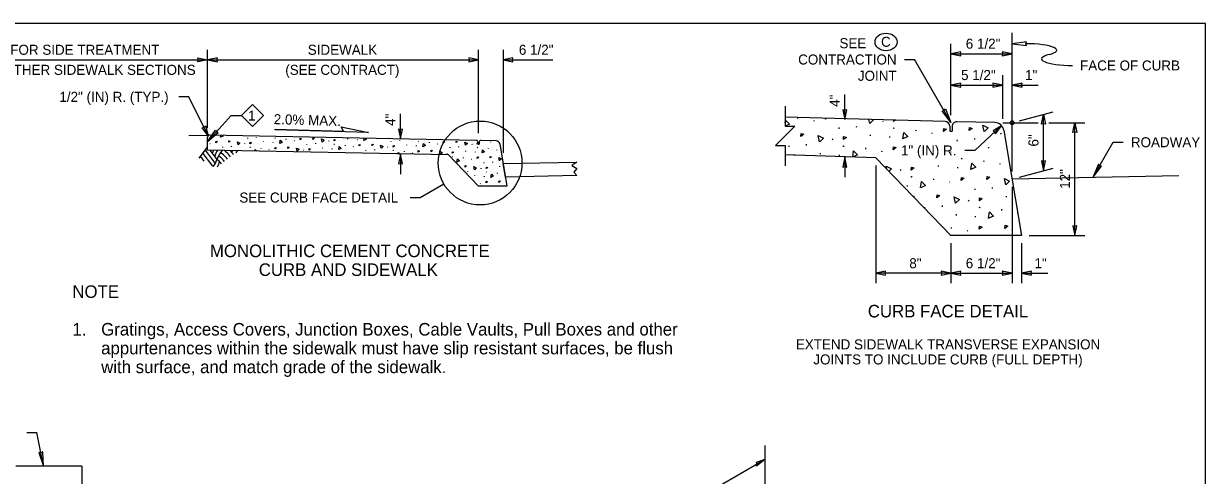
# Model space of a CAD drawing. Extents: x 99862 to 103151, y 100000 to 102076.
# Drawn here: x 101268 to 103151, y 101355 to 102076 of the extents above; entities that cross this region are included whole.
import ezdxf

# ---------------------------------------------------------------- set-up
doc = ezdxf.new("R2010")
doc.units = 0
for name, color, linetype in [('Level 1', 7, 'Continuous'), ('Level 13', 7, 'Continuous'), ('Level 15', 7, 'Continuous'), ('Level 20', 7, 'Continuous'), ('Level 27', 7, 'Continuous'), ('Level 28', 7, 'Continuous'), ('Level 34', 7, 'Continuous'), ('Level 6', 7, 'Continuous'), ('Level 60', 7, 'Continuous')]:
    doc.layers.add(name, color=color, linetype=linetype)

msp = doc.modelspace()

# ---------------------------------------------------------------- linework, layer by layer
at = {"layer": 'Level 1'}
msp.add_lwpolyline([(99862, 99999.5), (103151, 99999.5), (103151, 102075.5), (99862, 102075.5)], close=True, dxfattribs=at)
at = {"layer": 'Level 13'}
for p, q in [((102501.6, 101924.3), (102501.7, 101925.9)), ((102526.3, 101921.2), (102527.4, 101920.5)), ((102636.5, 101920.7), (102637.2, 101919.2)), ((102567.4, 101908), (102567.5, 101909.8)), ((102595.3, 101910.4), (102595.4, 101912.2)), ((102653.4, 101909.6), (102654.4, 101908.9)), ((102654.2, 101909.5), (102655.2, 101908.7)), ((102689.8, 101904.5), (102690, 101906.3)), ((102714.6, 101901.5), (102715.6, 101900.7)), ((102824.7, 101900.9), (102825.5, 101899.5)), ((101564.6, 101884.6), (101565.1, 101884.2)), ((101571.3, 101895.3), (101571.4, 101896.1)), ((101619.7, 101884.3), (101620, 101883.6)), ((101625.1, 101892.5), (101625.2, 101893.4)), ((101639.1, 101893.7), (101639.1, 101894.6)), ((101650.2, 101886.8), (101650.2, 101887.7)), ((101665.4, 101885.4), (101665.5, 101886.2)), ((101668.1, 101893.4), (101668.6, 101893)), ((101668.5, 101893.3), (101669, 101892.9)), ((101686.3, 101890.8), (101686.4, 101891.7)), ((101698.7, 101889.3), (101699.2, 101888.9)), ((101719.3, 101882.7), (101719.3, 101883.5)), ((101733.2, 101883.9), (101733.2, 101884.7)), ((101753.8, 101889), (101754.1, 101888.3)), ((101762.2, 101883.5), (101762.8, 101883.1)), ((101762.7, 101883.4), (101763.2, 101883)), ((101780.5, 101880.9), (101780.5, 101881.8)), ((101784.3, 101891.5), (101784.3, 101892.4)), ((101799.5, 101890), (101799.6, 101890.9)), ((101853.4, 101887.3), (101853.4, 101888.2)), ((101867.3, 101888.5), (101867.4, 101889.4)), ((101878.4, 101881.6), (101878.5, 101882.5)), ((101893.7, 101880.2), (101893.7, 101881)), ((101896.4, 101888.1), (101896.9, 101887.8)), ((101896.8, 101888.1), (101897.3, 101887.7)), ((101914.6, 101885.6), (101914.6, 101886.5)), ((101926.9, 101884), (101927.5, 101883.7)), ((101982, 101883.8), (101982.4, 101883)), ((102012.5, 101886.3), (102012.6, 101887.1)), ((102487.5, 101878.9), (102487.6, 101880.7)), ((102515.3, 101881.3), (102515.5, 101883.1)), ((102556.5, 101891.6), (102557.2, 101890.1)), ((102573.4, 101880.5), (102574.5, 101879.8)), ((102574.3, 101880.4), (102575.3, 101879.6)), ((102617.5, 101896.6), (102617.6, 101898.3)), ((102648, 101893.7), (102648.2, 101895.4)), ((102755.7, 101888.3), (102755.8, 101890)), ((102783.5, 101890.6), (102783.7, 101892.4)), ((101585.2, 101878), (101585.2, 101878.9)), ((101599.1, 101879.2), (101599.1, 101880.1)), ((101610.2, 101872.8), (101610.3, 101873.1)), ((101628.1, 101878.8), (101628.7, 101878.4)), ((101628.5, 101878.7), (101629.1, 101878.4)), ((101646.4, 101876.3), (101646.4, 101877.1)), ((101658.7, 101874.7), (101659.3, 101874.3)), ((101713.8, 101874.4), (101714.2, 101873.7)), ((101744.3, 101876.9), (101744.4, 101877.8)), ((101759.6, 101875.5), (101759.6, 101876.4)), ((101792.8, 101879.4), (101793.4, 101879)), ((101813.4, 101872.8), (101813.5, 101873.6)), ((101827.3, 101874), (101827.4, 101874.8)), ((101847.9, 101879.1), (101848.3, 101878.4)), ((101856.4, 101873.6), (101856.9, 101873.2)), ((101856.8, 101873.5), (101857.3, 101873.1)), ((101874.6, 101871), (101874.7, 101871.9)), ((101887, 101869.5), (101887.5, 101869.1)), ((101942.1, 101869.2), (101942.4, 101868.5)), ((101947.5, 101877.4), (101947.6, 101878.3)), ((101950.5, 101863.7), (101951, 101863.3)), ((101950.9, 101863.6), (101951.4, 101863.3)), ((101961.4, 101878.6), (101961.5, 101879.5)), ((101968.7, 101861.2), (101968.8, 101862)), ((101972.5, 101871.7), (101972.6, 101872.6)), ((101987.8, 101870.3), (101987.9, 101871.1)), ((101990.5, 101878.3), (101991, 101877.9)), ((101990.9, 101878.2), (101991.4, 101877.8)), ((102008.7, 101875.7), (102008.8, 101876.6)), ((102021.1, 101874.2), (102021.6, 101873.8)), ((102537.6, 101867.5), (102537.7, 101869.2)), ((102568.1, 101864.6), (102568.2, 101866.3)), ((102609.9, 101875.4), (102610, 101877.2)), ((102634.6, 101872.4), (102635.7, 101871.6)), ((102744.8, 101871.8), (102745.5, 101870.4)), ((102805.8, 101876.8), (102805.9, 101878.6)), ((101981.1, 101859.6), (101981.6, 101859.2)), ((101996.2, 101844.8), (101996.6, 101844.1)), ((102001.7, 101853), (102001.7, 101853.9)), ((102015.6, 101854.2), (102015.6, 101855.1)), ((102026.7, 101847.3), (102026.8, 101848.2)), ((102664.9, 101842.7), (102665.6, 101841.3)), ((102725.8, 101847.7), (102725.9, 101849.5)), ((102756.4, 101844.8), (102756.5, 101846.6)), ((102761.7, 101860.8), (102762.7, 101860)), ((102762.5, 101860.6), (102763.5, 101859.9)), ((102798.2, 101855.7), (102798.3, 101857.4)), ((102822.9, 101852.6), (102823.9, 101851.8)), ((101975.6, 101839.7), (101975.7, 101840.5)), ((101986.7, 101832.7), (101986.8, 101833.6)), ((102002, 101831.3), (102002.1, 101832.2)), ((102004.7, 101839.3), (102005.2, 101838.9)), ((102005.1, 101839.2), (102005.6, 101838.8)), ((102022.9, 101836.7), (102023, 101837.6)), ((102681.8, 101831.7), (102682.8, 101830.9)), ((102682.6, 101831.5), (102683.6, 101830.8)), ((102718.2, 101826.6), (102718.3, 101828.3)), ((101995.3, 101820.6), (101995.8, 101820.3)), ((102676.4, 101815.7), (102676.5, 101817.5)), ((102743, 101823.5), (102744, 101822.7)), ((102784.1, 101810.3), (102784.2, 101812)), ((102811.9, 101812.7), (102812, 101814.4)), ((102773.2, 101793.8), (102773.9, 101792.4)), ((102834.1, 101798.9), (102834.3, 101800.6)), ((102704.1, 101781.2), (102704.2, 101782.9)), ((102732, 101783.6), (102732.1, 101785.3)), ((102754.2, 101769.8), (102754.3, 101771.5)), ((102784.7, 101766.9), (102784.9, 101768.6)), ((102790.1, 101782.8), (102791.1, 101782.1)), ((102790.9, 101782.7), (102791.9, 101781.9)), ((102826.5, 101777.7), (102826.6, 101779.5)), ((102851.3, 101774.6), (102852, 101774.1)), ((102746.6, 101748.6), (102746.7, 101750.4)), ((102771.3, 101745.5), (102772.4, 101744.8))]:
    msp.add_line(p, q, dxfattribs=at)
for points in [[(102481.4, 101944), (102481.4, 101912), (102496.9, 101912), (102466, 101881), (102481.4, 101881), (102481.4, 101849)], [(102481.4, 101917.1), (102482.1, 101921.8), (102488.4, 101915.2), (102481.5, 101912)], [(102545.4, 101923.3), (102545.6, 101924.7)], [(102547.2, 101924.6), (102545.4, 101923.3)], [(102616.2, 101916.1), (102614.8, 101922.7)], [(102621.4, 101922.5), (102622.3, 101922.1), (102616.3, 101916.2)], [(102654.1, 101919.7), (102654.3, 101921.6)], [(102656.5, 101921.6), (102654.1, 101919.7)], [(102506.4, 101895.5), (102506.9, 101900.5), (102511.1, 101899.2), (102506.4, 101895.5)], [(102668.9, 101891.8), (102670.4, 101902), (102676.7, 101895.4), (102669.1, 101891.9)], [(102733.7, 101903.5), (102734.2, 101908.4), (102738.4, 101907.1), (102733.7, 101903.5)], [(102774.6, 101904.9), (102775.1, 101909.8), (102779.3, 101908.5), (102774.6, 101904.9)], [(102798.7, 101903.5), (102796.6, 101913.5), (102804.8, 101909.5), (102798.8, 101903.6)], [(101574.2, 101885.6), (101574.4, 101888.1), (101576.5, 101887.4), (101574.2, 101885.6)], [(101581.8, 101894.3), (101582.2, 101897.3)], [(101584.5, 101897.3), (101585.6, 101896.1), (101581.8, 101894.4)], [(101594.6, 101886.3), (101594.9, 101888.8), (101597, 101888.1), (101594.6, 101886.3)], [(101609.6, 101882), (101608.5, 101887), (101612.6, 101885), (101609.6, 101882.1)], [(101628.5, 101883.8), (101628.7, 101886.3), (101630.9, 101885.6), (101628.5, 101883.8)], [(101675.9, 101884.5), (101676.6, 101889.5), (101679.8, 101886.2), (101676, 101884.5)], [(101708.3, 101890.3), (101708.5, 101892.7), (101710.6, 101892.1), (101708.3, 101890.3)], [(101728.7, 101891), (101729, 101893.4), (101731.1, 101892.8), (101728.7, 101891)], [(101743.7, 101886.7), (101742.6, 101891.7), (101746.7, 101889.7), (101743.7, 101886.7)], [(101762.6, 101888.5), (101762.8, 101891), (101765, 101890.3), (101762.6, 101888.5)], [(101802.4, 101880.4), (101802.6, 101882.8), (101804.8, 101882.2), (101802.4, 101880.4)], [(101810, 101889.1), (101810.5, 101892.8)], [(101812.1, 101892.7), (101813.9, 101890.9), (101810.1, 101889.1)], [(101822.9, 101881.1), (101823.1, 101883.5), (101825.2, 101882.9), (101822.9, 101881.1)], [(101837.8, 101876.8), (101836.7, 101881.8), (101840.8, 101879.8), (101837.9, 101876.9)], [(101856.7, 101878.6), (101857, 101881.1), (101859.1, 101880.4), (101856.7, 101878.6)], [(101877.8, 101891.4), (101877.7, 101891.4)], [(101877.8, 101891.4), (101877.8, 101891.4)], [(101904.1, 101879.2), (101904.8, 101884.3), (101908, 101881), (101904.2, 101879.3)], [(101936.5, 101885.1), (101936.7, 101887.5), (101938.9, 101886.9), (101936.5, 101885.1)], [(101957, 101885.8), (101957.2, 101888.2), (101959.3, 101887.6), (101957, 101885.8)], [(101971.9, 101881.5), (101970.8, 101886.5), (101974.9, 101884.5), (101972, 101881.5)], [(101990.8, 101883.3), (101991.1, 101885.7), (101992.1, 101885.4)], [(101992.1, 101884.3), (101990.8, 101883.3)], [(102536.3, 101887), (102534.1, 101897), (102542.3, 101893), (102536.4, 101887.1)], [(102574.1, 101890.6), (102574.6, 101895.5), (102578.9, 101894.2), (102574.1, 101890.6)], [(101636.2, 101872.3), (101636.6, 101875), (101639.3, 101872.2)], [(101668.3, 101875.7), (101668.5, 101878.2), (101670.7, 101877.5), (101668.3, 101875.7)], [(101688.8, 101876.4), (101689, 101878.9), (101691.1, 101878.2), (101688.8, 101876.4)], [(101703.7, 101872.1), (101702.6, 101877.1), (101706.7, 101875.1), (101703.8, 101872.2)], [(101722.6, 101874), (101722.9, 101876.4), (101725, 101875.8), (101722.6, 101874)], [(101770, 101874.6), (101770.7, 101879.6), (101773.9, 101876.4), (101770.1, 101874.6)], [(101864.6, 101867.7), (101864.9, 101869.8), (101866.9, 101867.6)], [(101896.5, 101870.5), (101896.8, 101873), (101898.9, 101872.3), (101896.5, 101870.5)], [(101917, 101871.2), (101917.2, 101873.7), (101919.4, 101873), (101917, 101871.2)], [(101931.9, 101866.9), (101930.8, 101871.9), (101935, 101869.9), (101932, 101867)], [(101950.9, 101868.7), (101951.1, 101871.2), (101953.2, 101870.5), (101950.9, 101868.7)], [(101990.7, 101860.6), (101990.9, 101863.1), (101993, 101862.4), (101990.7, 101860.6)], [(101998.3, 101869.4), (101999, 101874.4), (102002.1, 101871.1), (101998.3, 101869.4)], [(102011.1, 101861.3), (102011.4, 101863.8), (102013.5, 101863.1), (102011.1, 101861.3)], [(102026.1, 101857), (102025, 101862), (102029.1, 101860), (102026.1, 101857.1)], [(102494.6, 101866), (102494.7, 101866.4), (102496.1, 101866)], [(102589, 101862.8), (102590.4, 101872.9), (102596.8, 101866.3), (102589.2, 101862.8)], [(102653.7, 101874.4), (102654.2, 101879.3), (102658.5, 101878), (102653.7, 101874.4)], [(101958.3, 101854.8), (101959, 101859.9), (101962.2, 101856.6), (101958.4, 101854.8)], [(101971.2, 101846.8), (101971.4, 101849.2), (101973.5, 101848.6), (101971.2, 101846.8)], [(101986.1, 101842.5), (101985, 101847.5), (101989.1, 101845.5), (101986.1, 101842.5)], [(102005, 101844.3), (102005.3, 101846.8), (102007.4, 101846.1), (102005, 101844.3)], [(102643.5, 101842.9), (102642.4, 101848.1), (102650.7, 101844.1), (102646.4, 101839.9)], [(102682.4, 101841.8), (102682.9, 101846.7), (102687.2, 101845.4), (102682.4, 101841.8)], [(102777.3, 101843), (102778.7, 101853.1), (102785, 101846.6), (102777.4, 101843)], [(102004.8, 101821.7), (102005.1, 101824.1), (102007.2, 101823.5), (102004.8, 101821.7)], [(102012.4, 101830.4), (102013.2, 101835.4), (102016.3, 101832.2), (102012.5, 101830.4)], [(102025.3, 101822.3), (102025.6, 101824.8), (102027.7, 101824.2), (102025.3, 101822.3)], [(102697.3, 101813.9), (102698.7, 101824), (102705.1, 101817.5), (102697.5, 101813.9)], [(102762.1, 101825.5), (102762.5, 101830.4), (102766.8, 101829.1), (102762.1, 101825.5)], [(102803, 101826.9), (102803.5, 101831.8), (102807.7, 101830.5), (102803, 101826.9)], [(102832.8, 101818.3), (102830.7, 101828.4), (102838.9, 101824.4), (102833, 101818.5)], [(102684.3, 101800.8), (102686.8, 101800.1), (102685.8, 101799.3)], [(102723, 101797.8), (102723.5, 101802.7), (102727.8, 101801.4), (102723, 101797.8)], [(102752.9, 101789.3), (102750.8, 101799.3), (102759, 101795.3), (102753, 101789.4)], [(102790.8, 101792.9), (102791.3, 101797.8), (102795.5, 101796.5), (102790.8, 101792.9)], [(102805.6, 101765), (102807, 101775.2), (102813.4, 101768.6), (102805.8, 101765.1)], [(102790.4, 101747.6), (102790.9, 101752.5), (102795.2, 101751.2), (102790.4, 101747.6)], [(102831.4, 101749), (102831.8, 101753.9), (102836.1, 101752.6), (102831.4, 101749)]]:
    msp.add_lwpolyline(points, dxfattribs=at)
at = {"layer": 'Level 15'}
for p, q in [((102843.1, 101839.5), (102843.1, 102060.6)), ((101560.9, 101908.8), (101560.9, 102033.8)), ((101992.9, 101901.1), (101992.9, 102033.8)), ((102031.9, 102033.8), (102031.9, 101869.4)), ((102745.6, 101929.5), (102745.6, 102043.5)), ((101153.6, 102017.8), (101560.9, 102017.8)), ((101560.9, 102017.8), (101992.9, 102017.8)), ((102031.9, 102017.8), (102110.9, 102017.8)), ((102671.6, 102018.3), (102687.6, 102018.3)), ((102745.6, 101918.1), (102687.6, 102018.3)), ((102745.6, 102027.5), (102843.1, 102027.5)), ((102828.1, 101923.5), (102828.1, 101993.5)), ((102745.6, 101977.5), (102828.1, 101977.5)), ((102843.1, 101977.5), (102884.7, 101977.5)), ((101531.3, 101958.8), (101515.3, 101958.8)), ((101562, 101896.8), (101531.3, 101958.8)), ((102576.3, 101922.5), (102576.3, 101962.5)), ((101560.4, 101886.7), (101598.8, 101928.9)), ((101598.8, 101928.9), (101614.8, 101928.9)), ((101868.3, 101891.6), (101868.3, 101931.6)), ((102854.7, 101920.6), (102908.5, 101935)), ((102893.1, 101840.9), (102893.1, 101930.9)), ((102783.7, 101873.3), (102826.3, 101913)), ((102828.1, 101917.5), (102884.3, 101917.5)), ((102901.8, 101917.5), (102959.1, 101917.5)), ((102943.1, 101737.5), (102943.1, 101917.5)), ((102971.7, 101830.1), (103004.2, 101886.3)), ((103004.2, 101886.3), (103020.2, 101886.3)), ((101868.3, 101867.6), (101868.3, 101835.6)), ((102576.3, 101862.5), (102576.3, 101830.5)), ((102783.7, 101873.3), (102767.7, 101873.3)), ((102625.6, 101849.5), (102625.6, 101661.5)), ((102854.7, 101830.6), (102908.5, 101845)), ((101899.8, 101798.2), (101937.3, 101819.9)), ((102843.1, 101815.5), (102843.1, 101661.5)), ((101883.8, 101798.2), (101899.8, 101798.2)), ((102870.1, 101737.5), (102959.1, 101737.5)), ((102745.6, 101725.5), (102745.6, 101661.5)), ((102858.1, 101725.5), (102858.1, 101661.5)), ((102745.6, 101677.5), (102625.6, 101677.5)), ((102745.6, 101677.5), (102843.1, 101677.5)), ((102858.1, 101677.5), (102899.7, 101677.5)), ((101272.7, 101423.6), (101289, 101423.6)), ((101299.7, 101370), (101289, 101423.6)), ((102449.4, 101278.5), (102449.4, 101402.9)), ((102334, 101314.3), (102449.4, 101380.9))]:
    msp.add_line(p, q, dxfattribs=at)
for points in [[(102843.1, 102043.5), (102865.9, 102040.5), (102864.8, 102043.5), (102865.9, 102046.5)], [(101560.9, 102017.8), (101545.2, 102014.7), (101545.9, 102017.8), (101545.2, 102020.9)], [(101560.9, 102017.8), (101576.6, 102014.7), (101575.9, 102017.8), (101576.6, 102020.9)], [(101992.9, 102017.8), (101977.2, 102020.9), (101977.9, 102017.8), (101977.2, 102014.7)], [(102031.9, 102017.8), (102047.6, 102014.7), (102046.9, 102017.8), (102047.6, 102020.9)], [(102745.6, 102027.5), (102761.3, 102024.4), (102760.6, 102027.5), (102761.3, 102030.6)], [(102843.1, 102027.5), (102827.3, 102030.6), (102828.1, 102027.5), (102827.3, 102024.4)], [(102745.6, 101977.5), (102761.3, 101974.4), (102760.6, 101977.5), (102761.3, 101980.6)], [(102828.1, 101977.5), (102812.3, 101980.6), (102813.1, 101977.5), (102812.3, 101974.4)], [(102843.1, 101977.5), (102858.8, 101974.4), (102858.1, 101977.5), (102858.8, 101980.6)], [(102576.3, 101922.5), (102579.4, 101938.2), (102576.3, 101937.5), (102573.2, 101938.2)], [(102745.6, 101918.1), (102731.6, 101936.4), (102734.7, 101937), (102736.7, 101939.4)], [(102893.1, 101930.9), (102896.1, 101915.2), (102893.1, 101915.9), (102890, 101915.2)], [(101562, 101896.8), (101552.3, 101909.6), (101555.3, 101910.3), (101557.8, 101912.3)], [(101560.4, 101886.7), (101573.5, 101905.6), (101575, 101902.8), (101578, 101901.5)], [(101868.3, 101891.6), (101871.4, 101907.3), (101868.3, 101906.6), (101865.2, 101907.3)], [(102826.2, 101912.8), (102812.6, 101904.4), (102815.2, 101902.6), (102816.8, 101899.9)], [(102943.1, 101917.5), (102946.2, 101901.8), (102943.1, 101902.5), (102940, 101901.8)], [(101868.3, 101867.6), (101865.2, 101851.9), (101868.3, 101852.6), (101871.4, 101851.9)], [(102576.3, 101862.5), (102573.2, 101846.8), (102576.3, 101847.5), (102579.4, 101846.8)], [(102893.1, 101840.9), (102896.1, 101856.6), (102893.1, 101855.9), (102890, 101856.6)], [(102971.7, 101830.1), (102985.7, 101848.3), (102982.6, 101848.9), (102980.6, 101851.3)], [(102943.1, 101737.5), (102946.2, 101753.2), (102943.1, 101752.5), (102940, 101753.2)], [(102625.6, 101677.5), (102641.3, 101674.4), (102640.6, 101677.5), (102641.3, 101680.6)], [(102745.6, 101677.5), (102729.8, 101680.6), (102730.6, 101677.5), (102729.8, 101674.4)], [(102745.6, 101677.5), (102761.3, 101674.4), (102760.6, 101677.5), (102761.3, 101680.6)], [(102843.1, 101677.5), (102827.3, 101680.6), (102828.1, 101677.5), (102827.3, 101674.4)], [(102858.1, 101677.5), (102873.8, 101674.4), (102873.1, 101677.5), (102873.8, 101680.6)], [(101299.7, 101370), (101298.2, 101392.9), (101295.4, 101391.3), (101292.3, 101391.8)], [(102449.4, 101380.9), (102435.7, 101370), (102436.4, 101373.4), (102435.7, 101376.1)]]:
    msp.add_lwpolyline(points, close=True, dxfattribs=at)
for centre, radius in [((101995.2, 101853.3), 66.8), ((102843.1, 101917.5), 3.08)]:
    msp.add_circle(centre, radius, dxfattribs=at)
for centre, start_param, end_param in [((102864.8, 102033), 2.427868, 4.712389), ((102939.3, 102019.3), 5.569461, 7.853982)]:
    msp.add_ellipse(centre, major_axis=(-49.3, 0), ratio=0.212611, start_param=start_param, end_param=end_param, dxfattribs=at)
at = {"layer": 'Level 20'}
for points in [[(101632.4, 101946.5), (101649.9, 101928.9), (101632.4, 101911.4), (101614.8, 101928.9)], [(101668.6, 101907.2), (101777.5, 101904.1), (101774, 101910.7), (101817.5, 101901.7), (101668.5, 101906)]]:
    msp.add_lwpolyline(points, close=True, dxfattribs=at)
msp.add_ellipse((102642.1, 102046.3), major_axis=(-17.5, 0), ratio=0.8, dxfattribs=at)
at = {"layer": 'Level 27'}
msp.add_lwpolyline([(102031.9, 101852.5), (102149.3, 101854.8), (102141.5, 101849.2), (102149.5, 101844.5), (102144.4, 101838.4), (102149.3, 101833.2), (102035.5, 101830.9)], close=True, dxfattribs=at)
at = {"layer": 'Level 28'}
msp.add_line((101530.9, 101897.2), (101560.9, 101897.8), dxfattribs=at)
at = {"layer": 'Level 34'}
for p, q in [((101560.9, 101897.8), (101561.8, 101896.8)), ((101547.8, 101860.9), (101560.9, 101878.4)), ((101549.8, 101863.7), (101555.2, 101856.4)), ((101553.5, 101868.6), (101568.7, 101848.3)), ((101557.2, 101873.6), (101573.1, 101852.4)), ((101564.6, 101873.7), (101575.8, 101858.7)), ((101599.4, 101870.4), (101601.3, 101873)), ((101606.3, 101869.7), (101608.6, 101872.8))]:
    msp.add_line(p, q, dxfattribs=at)
for centre, start, end in [((101600.5, 101862.2), 162.1651, 162.3566), ((101604.2, 101857.2), 154.2153, 162.3566), ((101607.9, 101852.3), 145.7189, 162.3566), ((101611.6, 101847.3), 136.2961, 162.3566), ((101558.6, 101832.5), 38.3659, 58.4874), ((101562.3, 101837.4), 40.9413, 59.3021), ((101566, 101842.4), 48.9597, 55.1915), ((101566, 101842.4), 33.1885, 48.9597), ((101562.3, 101837.4), 35.7783, 40.9414), ((101569.7, 101847.3), 30.5906, 43.1727), ((101540, 101870.1), 323.1058, 342.3566), ((101554.8, 101827.5), 40.9551, 56.0964), ((101543.7, 101865.2), 331.5055, 345.0113)]:
    msp.add_arc(centre, 37.6, start, end, dxfattribs=at)
at = {"layer": 'Level 6'}
for p, q in [((102736.3, 101919.3), (102481.4, 101926.5)), ((102815.6, 101917.7), (102755.1, 101918.9)), ((102743.7, 101911.8), (102743.7, 101904.1)), ((102743.7, 101904.1), (102747.4, 101904.1)), ((102747.4, 101911.4), (102747.4, 101904.1)), ((102830.1, 101905.2), (102858.1, 101737.5)), ((101560.9, 101873.8), (101560.9, 101894.7)), ((101989.2, 101889.2), (101563.9, 101897.7)), ((101992.1, 101886.2), (101992.1, 101883.1)), ((101992.1, 101883.1), (101993.6, 101883.1)), ((101993.6, 101886.1), (101993.6, 101883.1)), ((102020.9, 101888.6), (101996.7, 101889.1)), ((102026.7, 101883.6), (102037.9, 101816.5)), ((101944.9, 101866.1), (101560.9, 101873.8)), ((101944.9, 101866.1), (101992.9, 101816.5)), ((102625.6, 101861.5), (102481.4, 101866.5)), ((102625.6, 101861.5), (102745.6, 101737.5)), ((103108.6, 101832.8), (102843.1, 101827.5)), ((102037.9, 101816.5), (101992.9, 101816.5)), ((102858.1, 101737.5), (102745.6, 101737.5)), ((101360.3, 101370), (101255.3, 101370)), ((101360.3, 101370), (101360.3, 101244.2))]:
    msp.add_line(p, q, dxfattribs=at)
for centre, radius, start, end in [((102736.2, 101911.8), 7.5, 0, 88.8542), ((102754.9, 101911.4), 7.5, 88.8542, 180), ((102815.3, 101902.7), 15, 9.4623, 88.8542), ((101563.9, 101894.7), 3, 88.8542, 180), ((101989.1, 101886.2), 3, 0, 88.8542), ((101996.6, 101886.1), 3, 88.8542, 180), ((102020.8, 101882.6), 6, 9.4623, 88.8542)]:
    msp.add_arc(centre, radius, start, end, dxfattribs=at)
at = {"layer": 'Level 60'}
msp.add_line((103151, 102075.5), (103151, 102075.5), dxfattribs=at)

# ---------------------------------------------------------------- texts
at = {"layer": 'Level 20'}
for s, height, p in [('SEE       ', 16, (102567.9, 102036.3)), ('C', 16, (102634.2, 102038.5)), ('6 1/2"', 16, (102769.2, 102035.5)), ('SIDEWALK', 16, (101720.6, 102025.8)), ('6 1/2"', 16, (102057, 102025.8)), ('CONTRACTION', 16, (102502.1, 102010.3)), ('FACE OF CURB', 16, (102951.3, 102000.8)), ('(SEE CONTRACT)', 16, (101684.8, 101993.8)), ('JOINT', 16, (102597.2, 101984.3)), ('5 1/2"', 16, (102761.7, 101985.5)), ('1"', 16, (102863.7, 101985.5)), ('1', 16, (101625.5, 101920.9)), ('1" (IN) R.', 16, (102665.9, 101865.3)), ('ROADWAY', 16, (103032.3, 101878.4)), ('SEE CURB FACE DETAIL', 16, (101611.6, 101790.2)), ('MONOLITHIC CEMENT CONCRETE', 20, (101564.7, 101703.2)), ('CURB AND SIDEWALK', 20, (101642.5, 101673.2)), ('8"', 16, (102679.2, 101685.5)), ('6 1/2"', 16, (102769.2, 101685.5)), ('1"', 16, (102878.7, 101685.5)), ('NOTE', 20, (101345.5, 101638.2)), ('CURB FACE DETAIL', 20, (102613.1, 101607.1)), ('1.', 20, (101345.5, 101578.2)), ('Gratings, Access Covers, Junction Boxes, Cable Vaults, Pull Boxes and other', 20, (101391.4, 101578.2)), ('appurtenances within the sidewalk must have slip resistant surfaces, be flush', 20, (101391.4, 101548.2)), ('EXTEND SIDEWALK TRANSVERSE EXPANSION', 16, (102498.4, 101556.1)), ('JOINTS TO INCLUDE CURB (FULL DEPTH)', 16, (102526.3, 101532.1)), ('with surface, and match grade of the sidewalk.', 20, (101391.4, 101518.2))]:
    msp.add_text(s, height=height, dxfattribs=at).set_placement(p)
for s, rotation, p in [('FOR SIDE TREATMENT', 360, (101246.5, 102025.8)), ('SEE OTHER SIDEWALK SECTIONS', 360, (101186.5, 101993.8)), ('1/2" (IN) R. (TYP.)', 360, (101324.8, 101950.8)), ('4"', 90, (102568.3, 101942.8)), ('2.0% MAX.', 358.3445, (101666.2, 101915.3)), ('4"', 90, (101860.3, 101912.4)), ('6"', 90, (102885.1, 101879.5)), ('12"', 90, (102935.1, 101812.1))]:
    msp.add_text(s, height=16, rotation=rotation, dxfattribs=at).set_placement(p)

doc.saveas('drawing.dxf')
